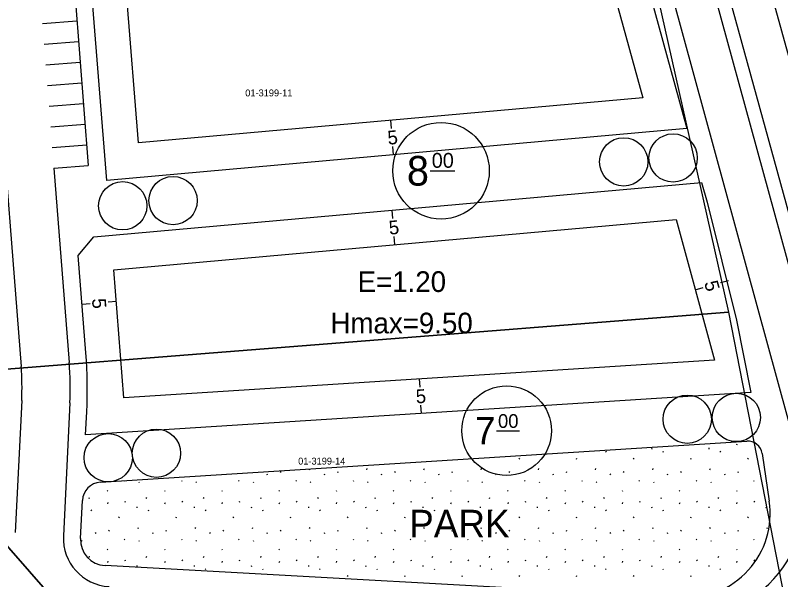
# Model space of a CAD drawing. Extents: x 419396 to 421519, y 4453567 to 4456767.
# Drawn here: x 421314.2 to 421425.2, y 4454826.5 to 4454908.3 of the extents above; entities that cross this region are included whole.
import ezdxf

# ---------------------------------------------------------------- set-up
doc = ezdxf.new("R2010")
doc.units = 0
for name, color, linetype in [('0_KADASTRO', 7, 'Continuous'), ('Level 20', 7, 'Continuous'), ('Level 28', 7, 'Continuous'), ('Level 29', 7, 'Continuous'), ('Level 30', 7, 'Continuous'), ('Level 41', 7, 'Continuous'), ('Level 55', 7, 'Continuous'), ('Level 58', 7, 'Continuous'), ('Level 61', 7, 'Continuous'), ('Level 62', 7, 'Continuous')]:
    doc.layers.add(name, color=color, linetype=linetype)

msp = doc.modelspace()

# ---------------------------------------------------------------- linework, layer by layer
at = {"layer": '0_KADASTRO'}
for points in [[(421297.61, 4454855.78), (421298.02, 4454877.83), (421306.52, 4454893.75), (421312.35, 4454909.46), (421317.66, 4454909.88), (421406.86, 4454913.27), (421417.65, 4454865.27)], [(421297.61, 4454855.78), (421298.02, 4454877.83), (421306.52, 4454893.75), (421312.35, 4454909.46), (421317.66, 4454909.88), (421406.86, 4454913.27), (421417.65, 4454865.27)], [(421297.61, 4454855.78), (421417.65, 4454865.27), (421429.39, 4454805.15), (421400.86, 4454807.28), (421374.76, 4454802.88), (421350.71, 4454801.96), (421332.63, 4454808.99), (421309.91, 4454834.93), (421299.79, 4454847.06)], [(421297.61, 4454855.78), (421417.65, 4454865.27), (421429.39, 4454805.15), (421400.86, 4454807.28), (421374.76, 4454802.88), (421350.71, 4454801.96), (421332.63, 4454808.99), (421309.91, 4454834.93), (421299.79, 4454847.06)], [(421297.3, 4454718.68), (421298.33, 4454743.86), (421298.65, 4454753.52), (421298.8, 4454768.82), (421298.12, 4454819), (421299.79, 4454847.06), (421309.91, 4454834.93), (421332.63, 4454808.99), (421350.71, 4454801.96), (421374.76, 4454802.88), (421400.86, 4454807.28), (421429.39, 4454805.15), (421423.5, 4454722.17), (421393.26, 4454602.31), (421372.96, 4454614.59), (421362.83, 4454633.4), (421361.48, 4454641.58), (421342.8, 4454669.52), (421331.29, 4454695.38), (421310.81, 4454712.23)], [(421297.3, 4454718.68), (421298.33, 4454743.86), (421298.65, 4454753.52), (421298.8, 4454768.82), (421298.12, 4454819), (421299.79, 4454847.06), (421309.91, 4454834.93), (421332.63, 4454808.99), (421350.71, 4454801.96), (421374.76, 4454802.88), (421400.86, 4454807.28), (421429.39, 4454805.15), (421423.5, 4454722.17), (421393.26, 4454602.31), (421372.96, 4454614.59), (421362.83, 4454633.4), (421361.48, 4454641.58), (421342.8, 4454669.52), (421331.29, 4454695.38), (421310.81, 4454712.23)]]:
    msp.add_lwpolyline(points, close=True, dxfattribs=at)
at = {"layer": 'Level 20'}
for p, q in [((421394.23, 4454936.33), (421405.19, 4454896.34)), ((421332.07, 4454889.8), (421328.87, 4454930.31)), ((421405.19, 4454896.34), (421332.07, 4454889.8)), ((421368.63, 4454893.07), (421368.74, 4454891.88)), ((421369.08, 4454888.09), (421368.97, 4454889.29)), ((421368.82, 4454880.04), (421368.93, 4454878.84)), ((421328.51, 4454871.41), (421410.03, 4454878.71)), ((421410.03, 4454878.71), (421415.62, 4454858.3)), ((421369.27, 4454875.06), (421369.16, 4454876.25)), ((421329.97, 4454852.86), (421328.51, 4454871.41)), ((421417.64, 4454869.82), (421416.49, 4454869.51)), ((421412.82, 4454868.5), (421413.98, 4454868.82)), ((421323.89, 4454866.41), (421325.08, 4454866.5)), ((421328.87, 4454866.8), (421327.67, 4454866.71)), ((421415.62, 4454858.3), (421329.97, 4454852.86)), ((421372.8, 4454855.58), (421372.87, 4454854.38)), ((421373.11, 4454850.59), (421373.04, 4454851.79))]:
    msp.add_line(p, q, dxfattribs=at)
at = {"layer": 'Level 28'}
for p, q in [((421324.41, 4454847.5), (421324.58, 4454850.81)), ((421326.57, 4454840.62), (421420.29, 4454846.57)), ((421422.52, 4454844.77), (421423.55, 4454837.88)), ((421323.69, 4454832.47), (421323.95, 4454837.96)), ((421410.83, 4454823.91), (421327.23, 4454828.54))]:
    msp.add_line(p, q, dxfattribs=at)
for centre, radius, start, end in [((421420.43, 4454844.46), 2.11, 8.5087, 93.6346), ((421326.74, 4454837.83), 2.8, 93.6346, 177.2286), ((421411.5, 4454836.07), 12.18, 266.8311, 8.5087), ((421327.44, 4454832.29), 3.76, 177.2286, 266.8311)]:
    msp.add_arc(centre, radius, start, end, dxfattribs=at)
at = {"layer": 'Level 29'}
for p, q in [((421397.94, 4454941.69), (421411.59, 4454891.9)), ((421327.48, 4454884.37), (421323.49, 4454934.84)), ((421411.59, 4454891.9), (421327.48, 4454884.37)), ((421325.61, 4454876.17), (421413.74, 4454884.06)), ((421413.74, 4454884.06), (421414.52, 4454881.2)), ((421414.52, 4454881.2), (421418.78, 4454864.1)), ((421323.33, 4454873.47), (421325.61, 4454876.17)), ((421324.44, 4454859.35), (421323.33, 4454873.47)), ((421418.78, 4454864.1), (421420.86, 4454853.62)), ((421324.52, 4454858.28), (421324.44, 4454859.35)), ((421324.58, 4454857.21), (421324.52, 4454858.28)), ((421324.62, 4454856.15), (421324.58, 4454857.21)), ((421324.65, 4454855.08), (421324.62, 4454856.15)), ((421324.65, 4454854.01), (421324.65, 4454855.08)), ((421420.86, 4454853.62), (421324.41, 4454847.5)), ((421324.64, 4454852.94), (421324.65, 4454854.01)), ((421324.62, 4454851.87), (421324.64, 4454852.94)), ((421324.58, 4454850.81), (421324.62, 4454851.87))]:
    msp.add_line(p, q, dxfattribs=at)
at = {"layer": 'Level 41'}
for p, q in [((421418.84, 4454846.02), (421418.91, 4454846.18)), ((421421.31, 4454846.37), (421421.38, 4454846.26)), ((421399.82, 4454845.11), (421399.89, 4454845)), ((421406.48, 4454845.58), (421406.5, 4454845.42)), ((421408.11, 4454845.11), (421408.18, 4454845)), ((421414.77, 4454845.58), (421414.79, 4454845.42)), ((421416.4, 4454845.11), (421416.47, 4454845)), ((421387.29, 4454843.96), (421387.36, 4454844.12)), ((421395.58, 4454843.96), (421395.65, 4454844.12)), ((421403.87, 4454843.96), (421403.94, 4454844.12)), ((421412.16, 4454843.96), (421412.24, 4454844.12)), ((421420.46, 4454843.96), (421420.53, 4454844.12)), ((421356.89, 4454842.43), (421356.94, 4454842.55)), ((421365.18, 4454842.43), (421365.25, 4454842.59)), ((421373.47, 4454842.43), (421373.54, 4454842.59)), ((421381.76, 4454842.43), (421381.83, 4454842.59)), ((421390.06, 4454842.43), (421390.13, 4454842.59)), ((421398.35, 4454842.43), (421398.42, 4454842.59)), ((421406.64, 4454842.43), (421406.71, 4454842.59)), ((421414.94, 4454842.43), (421415.01, 4454842.59)), ((421350.69, 4454841.82), (421350.76, 4454841.71)), ((421352.68, 4454842.02), (421352.75, 4454842.18)), ((421358.98, 4454841.82), (421359.05, 4454841.71)), ((421360.97, 4454842.02), (421361.04, 4454842.18)), ((421367.27, 4454841.82), (421367.34, 4454841.71)), ((421369.26, 4454842.02), (421369.33, 4454842.18)), ((421375.57, 4454841.82), (421375.64, 4454841.71)), ((421377.55, 4454842.02), (421377.63, 4454842.18)), ((421383.86, 4454841.82), (421383.93, 4454841.71)), ((421385.85, 4454842.02), (421385.92, 4454842.18)), ((421392.15, 4454841.82), (421392.22, 4454841.71)), ((421394.14, 4454842.02), (421394.21, 4454842.18)), ((421400.45, 4454841.82), (421400.52, 4454841.71)), ((421402.43, 4454842.02), (421402.5, 4454842.18)), ((421408.74, 4454841.82), (421408.81, 4454841.71)), ((421410.73, 4454842.02), (421410.8, 4454842.18)), ((421417.03, 4454841.82), (421417.1, 4454841.71)), ((421419.02, 4454842.02), (421419.09, 4454842.18)), ((421330.05, 4454840.84), (421330.09, 4454840.78)), ((421332.12, 4454840.69), (421332.19, 4454840.59)), ((421338.31, 4454840.89), (421338.38, 4454840.78)), ((421340.41, 4454840.69), (421340.48, 4454840.59)), ((421346.6, 4454840.89), (421346.67, 4454840.78)), ((421348.7, 4454840.69), (421348.77, 4454840.59)), ((421354.9, 4454840.89), (421354.97, 4454840.78)), ((421356.99, 4454840.69), (421357.07, 4454840.59)), ((421363.19, 4454840.89), (421363.26, 4454840.78)), ((421365.29, 4454840.69), (421365.36, 4454840.59)), ((421371.48, 4454840.89), (421371.55, 4454840.78)), ((421373.58, 4454840.69), (421373.65, 4454840.59)), ((421379.77, 4454840.89), (421379.85, 4454840.78)), ((421381.87, 4454840.69), (421381.94, 4454840.59)), ((421388.07, 4454840.89), (421388.14, 4454840.78)), ((421390.17, 4454840.69), (421390.24, 4454840.59)), ((421396.36, 4454840.89), (421396.43, 4454840.78)), ((421398.46, 4454840.69), (421398.53, 4454840.59)), ((421404.65, 4454840.89), (421404.72, 4454840.78)), ((421406.75, 4454840.69), (421406.82, 4454840.59)), ((421412.95, 4454840.89), (421413.02, 4454840.78)), ((421415.05, 4454840.69), (421415.12, 4454840.59)), ((421421.24, 4454840.89), (421421.31, 4454840.78)), ((421327.56, 4454839.43), (421327.63, 4454839.33)), ((421335.85, 4454839.43), (421335.92, 4454839.33)), ((421344.15, 4454839.43), (421344.22, 4454839.33)), ((421352.44, 4454839.43), (421352.51, 4454839.33)), ((421360.73, 4454839.43), (421360.8, 4454839.33)), ((421369.03, 4454839.43), (421369.1, 4454839.33)), ((421377.32, 4454839.43), (421377.39, 4454839.33)), ((421385.61, 4454839.43), (421385.68, 4454839.33)), ((421393.9, 4454839.43), (421393.98, 4454839.33)), ((421402.2, 4454839.43), (421402.27, 4454839.33)), ((421410.49, 4454839.43), (421410.56, 4454839.33)), ((421418.78, 4454839.43), (421418.85, 4454839.33)), ((421324.92, 4454838.24), (421324.99, 4454838.4)), ((421333.21, 4454838.24), (421333.28, 4454838.4)), ((421341.51, 4454838.24), (421341.58, 4454838.4)), ((421349.8, 4454838.24), (421349.87, 4454838.4)), ((421358.09, 4454838.24), (421358.16, 4454838.4)), ((421366.38, 4454838.24), (421366.46, 4454838.4)), ((421374.68, 4454838.24), (421374.75, 4454838.4)), ((421382.97, 4454838.24), (421383.04, 4454838.4)), ((421391.26, 4454838.24), (421391.33, 4454838.4)), ((421399.56, 4454838.24), (421399.63, 4454838.4)), ((421407.85, 4454838.24), (421407.92, 4454838.4)), ((421416.14, 4454838.24), (421416.21, 4454838.4)), ((421327.62, 4454837.51), (421327.69, 4454837.67)), ((421330.08, 4454837.86), (421330.15, 4454837.75)), ((421331.84, 4454837.07), (421331.86, 4454836.91)), ((421335.91, 4454837.51), (421335.98, 4454837.67)), ((421338.38, 4454837.86), (421338.45, 4454837.75)), ((421340.13, 4454837.07), (421340.15, 4454836.91)), ((421344.2, 4454837.51), (421344.28, 4454837.67)), ((421346.67, 4454837.86), (421346.74, 4454837.75)), ((421348.43, 4454837.07), (421348.45, 4454836.91)), ((421352.5, 4454837.51), (421352.57, 4454837.67)), ((421354.96, 4454837.86), (421355.03, 4454837.75)), ((421356.72, 4454837.07), (421356.74, 4454836.91)), ((421360.79, 4454837.51), (421360.86, 4454837.67)), ((421363.26, 4454837.86), (421363.33, 4454837.75)), ((421365.01, 4454837.07), (421365.03, 4454836.91)), ((421369.08, 4454837.51), (421369.16, 4454837.67)), ((421371.55, 4454837.86), (421371.62, 4454837.75)), ((421373.31, 4454837.07), (421373.32, 4454836.91)), ((421377.38, 4454837.51), (421377.45, 4454837.67)), ((421379.84, 4454837.86), (421379.91, 4454837.75)), ((421381.6, 4454837.07), (421381.62, 4454836.91)), ((421385.67, 4454837.51), (421385.74, 4454837.67)), ((421388.13, 4454837.86), (421388.21, 4454837.75)), ((421389.89, 4454837.07), (421389.91, 4454836.91)), ((421393.96, 4454837.51), (421394.03, 4454837.67)), ((421396.43, 4454837.86), (421396.5, 4454837.75)), ((421398.19, 4454837.07), (421398.2, 4454836.91)), ((421402.26, 4454837.51), (421402.33, 4454837.67)), ((421404.72, 4454837.86), (421404.79, 4454837.75)), ((421406.48, 4454837.07), (421406.5, 4454836.91)), ((421410.55, 4454837.51), (421410.62, 4454837.67)), ((421413.01, 4454837.86), (421413.08, 4454837.75)), ((421414.77, 4454837.07), (421414.79, 4454836.91)), ((421418.84, 4454837.51), (421418.91, 4454837.67)), ((421421.31, 4454837.86), (421421.38, 4454837.75)), ((421423.06, 4454837.07), (421423.08, 4454836.91)), ((421325.18, 4454836.6), (421325.25, 4454836.49)), ((421333.47, 4454836.6), (421333.54, 4454836.49)), ((421341.76, 4454836.6), (421341.83, 4454836.49)), ((421350.06, 4454836.6), (421350.13, 4454836.49)), ((421358.35, 4454836.6), (421358.42, 4454836.49)), ((421366.64, 4454836.6), (421366.71, 4454836.49)), ((421374.94, 4454836.6), (421375.01, 4454836.49)), ((421383.23, 4454836.6), (421383.3, 4454836.49)), ((421391.52, 4454836.6), (421391.59, 4454836.49)), ((421399.82, 4454836.6), (421399.89, 4454836.49)), ((421408.11, 4454836.6), (421408.18, 4454836.49)), ((421416.4, 4454836.6), (421416.47, 4454836.49)), ((421329.23, 4454835.45), (421329.31, 4454835.61)), ((421337.53, 4454835.45), (421337.6, 4454835.61)), ((421345.82, 4454835.45), (421345.89, 4454835.61)), ((421354.11, 4454835.45), (421354.19, 4454835.61)), ((421362.41, 4454835.45), (421362.48, 4454835.61)), ((421370.7, 4454835.45), (421370.77, 4454835.61)), ((421378.99, 4454835.45), (421379.06, 4454835.61)), ((421387.29, 4454835.45), (421387.36, 4454835.61)), ((421395.58, 4454835.45), (421395.65, 4454835.61)), ((421403.87, 4454835.45), (421403.94, 4454835.61)), ((421412.16, 4454835.45), (421412.24, 4454835.61)), ((421420.46, 4454835.45), (421420.53, 4454835.61)), ((421323.76, 4454834.04), (421323.78, 4454834.08)), ((421327.8, 4454833.51), (421327.87, 4454833.67)), ((421332.01, 4454833.92), (421332.08, 4454834.08)), ((421336.09, 4454833.51), (421336.16, 4454833.67)), ((421340.3, 4454833.92), (421340.37, 4454834.08)), ((421344.38, 4454833.51), (421344.45, 4454833.67)), ((421348.59, 4454833.92), (421348.66, 4454834.08)), ((421352.68, 4454833.51), (421352.75, 4454833.67)), ((421356.89, 4454833.92), (421356.96, 4454834.08)), ((421360.97, 4454833.51), (421361.04, 4454833.67)), ((421365.18, 4454833.92), (421365.25, 4454834.08)), ((421369.26, 4454833.51), (421369.33, 4454833.67)), ((421373.47, 4454833.92), (421373.54, 4454834.08)), ((421377.55, 4454833.51), (421377.63, 4454833.67)), ((421381.76, 4454833.92), (421381.83, 4454834.08)), ((421385.85, 4454833.51), (421385.92, 4454833.67)), ((421390.06, 4454833.92), (421390.13, 4454834.08)), ((421394.14, 4454833.51), (421394.21, 4454833.67)), ((421398.35, 4454833.92), (421398.42, 4454834.08)), ((421402.43, 4454833.51), (421402.5, 4454833.67)), ((421406.64, 4454833.92), (421406.71, 4454834.08)), ((421410.73, 4454833.51), (421410.8, 4454833.67)), ((421414.94, 4454833.92), (421415.01, 4454834.08)), ((421419.02, 4454833.51), (421419.09, 4454833.67)), ((421423.23, 4454833.92), (421423.3, 4454834.08)), ((421325.81, 4454833.31), (421325.88, 4454833.2)), ((421334.1, 4454833.31), (421334.17, 4454833.2)), ((421342.39, 4454833.31), (421342.47, 4454833.2)), ((421350.69, 4454833.31), (421350.76, 4454833.2)), ((421358.98, 4454833.31), (421359.05, 4454833.2)), ((421367.27, 4454833.31), (421367.34, 4454833.2)), ((421375.57, 4454833.31), (421375.64, 4454833.2)), ((421383.86, 4454833.31), (421383.93, 4454833.2)), ((421392.15, 4454833.31), (421392.22, 4454833.2)), ((421400.45, 4454833.31), (421400.52, 4454833.2)), ((421408.74, 4454833.31), (421408.81, 4454833.2)), ((421417.03, 4454833.31), (421417.1, 4454833.2)), ((421323.82, 4454832.18), (421323.89, 4454832.08)), ((421330.02, 4454832.38), (421330.09, 4454832.27)), ((421332.12, 4454832.18), (421332.19, 4454832.08)), ((421338.31, 4454832.38), (421338.38, 4454832.27)), ((421340.41, 4454832.18), (421340.48, 4454832.08)), ((421346.6, 4454832.38), (421346.67, 4454832.27)), ((421348.7, 4454832.18), (421348.77, 4454832.08)), ((421354.9, 4454832.38), (421354.97, 4454832.27)), ((421356.99, 4454832.18), (421357.07, 4454832.08)), ((421363.19, 4454832.38), (421363.26, 4454832.27)), ((421365.29, 4454832.18), (421365.36, 4454832.08)), ((421371.48, 4454832.38), (421371.55, 4454832.27)), ((421373.58, 4454832.18), (421373.65, 4454832.08)), ((421379.77, 4454832.38), (421379.85, 4454832.27)), ((421381.87, 4454832.18), (421381.94, 4454832.08)), ((421388.07, 4454832.38), (421388.14, 4454832.27)), ((421390.17, 4454832.18), (421390.24, 4454832.08)), ((421396.36, 4454832.38), (421396.43, 4454832.27)), ((421398.46, 4454832.18), (421398.53, 4454832.08)), ((421404.65, 4454832.38), (421404.72, 4454832.27)), ((421406.75, 4454832.18), (421406.82, 4454832.08)), ((421412.95, 4454832.38), (421413.02, 4454832.27)), ((421415.05, 4454832.18), (421415.12, 4454832.08)), ((421421.24, 4454832.38), (421421.31, 4454832.27)), ((421327.56, 4454830.92), (421327.63, 4454830.82)), ((421335.85, 4454830.92), (421335.92, 4454830.82)), ((421344.15, 4454830.92), (421344.22, 4454830.82)), ((421352.44, 4454830.92), (421352.51, 4454830.82)), ((421360.73, 4454830.92), (421360.8, 4454830.82)), ((421369.03, 4454830.92), (421369.1, 4454830.82)), ((421377.32, 4454830.92), (421377.39, 4454830.82)), ((421385.61, 4454830.92), (421385.68, 4454830.82)), ((421393.9, 4454830.92), (421393.98, 4454830.82)), ((421402.2, 4454830.92), (421402.27, 4454830.82)), ((421410.49, 4454830.92), (421410.56, 4454830.82)), ((421418.78, 4454830.92), (421418.85, 4454830.82)), ((421324.92, 4454829.73), (421324.99, 4454829.89)), ((421327.62, 4454829), (421327.69, 4454829.16)), ((421330.08, 4454829.35), (421330.15, 4454829.24)), ((421333.21, 4454829.73), (421333.28, 4454829.89)), ((421335.91, 4454829), (421335.98, 4454829.16)), ((421338.38, 4454829.35), (421338.45, 4454829.24)), ((421341.51, 4454829.73), (421341.58, 4454829.89)), ((421344.2, 4454829), (421344.28, 4454829.16)), ((421346.67, 4454829.35), (421346.74, 4454829.24)), ((421349.8, 4454829.73), (421349.87, 4454829.89)), ((421352.5, 4454829), (421352.57, 4454829.16)), ((421354.96, 4454829.35), (421355.03, 4454829.24)), ((421358.09, 4454829.73), (421358.16, 4454829.89)), ((421360.79, 4454829), (421360.86, 4454829.16)), ((421363.26, 4454829.35), (421363.33, 4454829.24)), ((421366.38, 4454829.73), (421366.46, 4454829.89)), ((421369.08, 4454829), (421369.16, 4454829.16)), ((421371.55, 4454829.35), (421371.62, 4454829.24)), ((421374.68, 4454829.73), (421374.75, 4454829.89)), ((421377.38, 4454829), (421377.45, 4454829.16)), ((421379.84, 4454829.35), (421379.91, 4454829.24)), ((421382.97, 4454829.73), (421383.04, 4454829.89)), ((421385.67, 4454829), (421385.74, 4454829.16)), ((421388.13, 4454829.35), (421388.21, 4454829.24)), ((421391.26, 4454829.73), (421391.33, 4454829.89)), ((421393.96, 4454829), (421394.03, 4454829.16)), ((421396.43, 4454829.35), (421396.5, 4454829.24)), ((421399.56, 4454829.73), (421399.63, 4454829.89)), ((421402.26, 4454829), (421402.33, 4454829.16)), ((421404.72, 4454829.35), (421404.79, 4454829.24)), ((421407.85, 4454829.73), (421407.92, 4454829.89)), ((421410.55, 4454829), (421410.62, 4454829.16)), ((421413.01, 4454829.35), (421413.08, 4454829.24)), ((421416.14, 4454829.73), (421416.21, 4454829.89)), ((421418.84, 4454829), (421418.91, 4454829.16)), ((421421.31, 4454829.35), (421421.38, 4454829.24)), ((421331.84, 4454828.56), (421331.86, 4454828.4)), ((421340.13, 4454828.56), (421340.15, 4454828.4)), ((421341.76, 4454828.09), (421341.83, 4454827.98)), ((421348.43, 4454828.56), (421348.45, 4454828.4)), ((421350.06, 4454828.09), (421350.13, 4454827.98)), ((421356.72, 4454828.56), (421356.74, 4454828.4)), ((421358.35, 4454828.09), (421358.42, 4454827.98)), ((421365.01, 4454828.56), (421365.03, 4454828.4)), ((421366.64, 4454828.09), (421366.71, 4454827.98)), ((421373.31, 4454828.56), (421373.32, 4454828.4)), ((421374.94, 4454828.09), (421375.01, 4454827.98)), ((421381.6, 4454828.56), (421381.62, 4454828.4)), ((421383.23, 4454828.09), (421383.3, 4454827.98)), ((421389.89, 4454828.56), (421389.91, 4454828.4)), ((421391.52, 4454828.09), (421391.59, 4454827.98)), ((421398.19, 4454828.56), (421398.2, 4454828.4)), ((421399.82, 4454828.09), (421399.89, 4454827.98)), ((421406.48, 4454828.56), (421406.5, 4454828.4)), ((421408.11, 4454828.09), (421408.18, 4454827.98)), ((421414.77, 4454828.56), (421414.79, 4454828.4)), ((421416.4, 4454828.09), (421416.47, 4454827.98)), ((421354.16, 4454827.05), (421354.19, 4454827.1)), ((421362.41, 4454826.94), (421362.48, 4454827.1)), ((421370.7, 4454826.94), (421370.77, 4454827.1)), ((421378.99, 4454826.94), (421379.06, 4454827.1)), ((421387.29, 4454826.94), (421387.36, 4454827.1)), ((421395.58, 4454826.94), (421395.65, 4454827.1)), ((421403.87, 4454826.94), (421403.94, 4454827.1)), ((421412.16, 4454826.94), (421412.24, 4454827.1))]:
    msp.add_line(p, q, dxfattribs=at)
at = {"layer": 'Level 55'}
for centre in [(421402.44, 4454887.05), (421409.6, 4454887.61), (421337.09, 4454881.43), (421329.79, 4454880.68), (421411.65, 4454849.75), (421418.77, 4454850.01), (421334.68, 4454844.82), (421327.69, 4454844.17)]:
    msp.add_circle(centre, 3.5, dxfattribs=at)
at = {"layer": 'Level 58'}
for p, q in [((421374.39, 4454885.76), (421377.94, 4454885.76)), ((421384.01, 4454848.09), (421387.31, 4454848.09))]:
    msp.add_line(p, q, dxfattribs=at)
for centre, radius in [((421375.95, 4454885.76), 7), ((421385.46, 4454848.09), 6.5)]:
    msp.add_circle(centre, radius, dxfattribs=at)
at = {"layer": 'Level 62'}
for p, q in [((421432.06, 4454851.29), (421377.52, 4455050.31)), ((421433.99, 4454851.82), (421379.49, 4455050.65)), ((421439.78, 4454853.41), (421386.03, 4455049.48)), ((421428.12, 4454842.97), (421374.21, 4455040.42)), ((421305.11, 4454983.33), (421315.07, 4454857.4)), ((421321.26, 4454931.4), (421324.8, 4454886.54)), ((421318.16, 4454907.08), (421323.15, 4454907.47)), ((421318.4, 4454904.09), (421323.39, 4454904.48)), ((421318.64, 4454901.1), (421323.62, 4454901.49)), ((421318.87, 4454898.11), (421323.86, 4454898.5)), ((421319.11, 4454895.12), (421324.09, 4454895.51)), ((421319.35, 4454892.12), (421324.33, 4454892.52)), ((421319.58, 4454889.13), (421324.57, 4454889.53)), ((421319.82, 4454886.14), (421324.8, 4454886.54)), ((421319.82, 4454886.14), (421322.05, 4454857.96)), ((421315.14, 4454852.48), (421314.22, 4454833.31)), ((421322.14, 4454852.12), (421321.2, 4454832.83))]:
    msp.add_line(p, q, dxfattribs=at)
for centre, radius, start, end in [((421276.5, 4454854.35), 38.69, 357.2286, 4.5195), ((421276.29, 4454854.34), 45.9, 357.2286, 4.5195), ((421411.29, 4454838.36), 17.45, 266.8311, 15.3284), ((421328.19, 4454832.49), 7, 177.2286, 266.8311)]:
    msp.add_arc(centre, radius, start, end, dxfattribs=at)

# ---------------------------------------------------------------- texts
at = {"layer": '0_KADASTRO'}
for s, p in [('01-3199-11', (421347.56, 4454896.54)), ('01-3199-11', (421347.56, 4454896.54)), ('01-3199-14', (421355.23, 4454843.18)), ('01-3199-14', (421355.23, 4454843.18))]:
    msp.add_text(s, height=1, dxfattribs=at).set_placement(p)
at = {"layer": 'Level 20'}
for rotation, p in [(5.1122, (421368.28, 4454889.53)), (5.1123, (421368.47, 4454876.49)), (285.3284, (421414.09, 4454869.54)), (274.5195, (421325.33, 4454867.19)), (3.6346, (421372.35, 4454852.04))]:
    msp.add_text('5', height=2, rotation=rotation, dxfattribs=at).set_placement(p)
at = {"layer": 'Level 30'}
for s, p in [('E=1.20', (421363.85, 4454868.19)), ('Hmax=9.50', (421359.92, 4454862.19))]:
    msp.add_text(s, height=3, dxfattribs=at).set_placement(p)
at = {"layer": 'Level 58'}
for s, height, p in [('8', 4.3, (421371, 4454883.61)), ('00', 2.152, (421374.6, 4454886.19)), ('00', 1.998, (421384.21, 4454848.49)), ('7', 4, (421380.87, 4454846.09))]:
    msp.add_text(s, height=height, dxfattribs=at).set_placement(p)
at = {"layer": 'Level 61'}
msp.add_text('PARK', height=4, dxfattribs=at).set_placement((421371.33, 4454832.62))

doc.saveas('drawing.dxf')
